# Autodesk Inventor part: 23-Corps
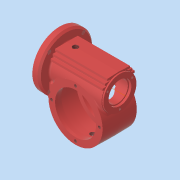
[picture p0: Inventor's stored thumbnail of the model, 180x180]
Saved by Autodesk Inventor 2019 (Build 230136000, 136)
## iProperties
Created: 2023-02
Part Number: 23-Corps
Material: Générique
Document SubType Name: Modeling
Designer: Thier
Density: 1 g/cm^3
Appearance: Lisse - Rouge
Author: Thier
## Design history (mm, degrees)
revolve "Révolution1" stored, may be unused: angle "d8" = 90 deg
sketch "Esquisse2"
  geometry: L1 (108.863, -25)-(108.863, 25) reference; C1 r 48 at (60.863, -40.6); 1 further point
  constraints: 1 centre point
  dimensions: "d9" = 40.6 vertical distance of C1.centre point (0, 0); "d10" = 96 diameter of C1; "d11" = 48 distance from line of C1.centre L1
extrude "Extrusion1" join sketch "Esquisse2" stored distance "d12" = 60; taper "d13" = -1 deg
sketch "Esquisse3"
  geometry: C1 r 46 at (60.863, -40.6); 5 further points
  constraints: 1 centre point, 2 other
  dimensions: "d14" = 92 diameter of C1
extrude "Extrusion2" cut sketch "Esquisse3" stored distance "d15" = 34; taper "d16" = -1 deg
sketch "Esquisse4"
  geometry: C1 r 38 at (60.863, -40.6); A1 r 48 centre (60.863, -40.6) between (13.437, -48) and (107.44, -29) reference; 2 further points
  constraints: 1 centre point, 1 concentric
  dimensions: "d17" = 76 diameter of C1
extrude "Extrusion3" cut sketch "Esquisse4" stored distance "d18" = 50; taper "d19" = 0 deg
sketch "Esquisse5"
  geometry: C1 r 36 at (60.863, -40.6); 5 further points
  constraints: 1 centre point, 2 other
  dimensions: "d20" = 72 diameter of C1
extrude "Extrusion4" cut sketch "Esquisse5" extent not by distance; stored distance "d21" = 50; taper "d22" = 0 deg
sketch "Esquisse9"
  geometry: C1 r 29 at (0, 0); C2 r 18 at (0, 0); 1 further point
  constraints: 2 centre point, 2 coincident
  dimensions: "d37" = 58 diameter of C1; "d38" = 36 diameter of C2
extrude "Extrusion7" join sketch "Esquisse9" distance "d39" = 19; taper "d40" = 0 deg
sketch "Esquisse12"
  geometry: C1 r 36 at (-60.863, -40.6); C2 r 36 at (-60.863, -40.6) reference; 1 further point
  constraints: 1 centre point, 1 concentric
  dimensions: "d47" = 72 diameter of C1
extrude "Extrusion10" cut sketch "Esquisse12" extent not by distance; stored distance "d48" = 8; taper "d49" = 0 deg
sketch "Esquisse13"
  geometry: C1 r 38 at (0, 0); C2 r 36 at (0, 0) reference; 1 further point
  constraints: 1 centre point, 1 concentric
  dimensions: "d50" = 76 diameter of C1
extrude "Extrusion11" cut sketch "Esquisse13" distance "d51" = 50; taper "d52" = 0 deg
chamfer "Chanfrein1" distance "d53" = 8; stored, may be unused: second distance "d54" = 1, angle "d55" = 45 deg
chamfer "Chanfrein2" distance "d56" = 8; stored, may be unused: second distance "d57" = 1, angle "d58" = 45 deg
chamfer "Chanfrein3" distance "d59" = 3; stored, may be unused: second distance "d60" = 1, angle "d61" = 45 deg
sketch "Esquisse14" dims "d63" = 84
  geometry: L1 (60.863, -40.6)-(60.863, 1.4); L2 (60.863, -38.664)-(60.863, 43.315); C1 r 36 at (60.863, -40.6) reference; 3 further points
  constraints: 4 end point, 2 coincident, 1 point on line, 1 vertical, 1 vertical alignment, 2 other
  dimensions: "d74" = 0 distance between parallel lines of L2 L1
hole "Perçage1" sketch "Esquisse14" at (60.863, 1.4) diameter "d64" = 4.917; stored, may be unused: countersink angle "d68" = 90 deg, drill point angle "d70" = 118 deg; dims "d65" = 12, "d66" = 4, "d67" = 2, "d69" = 8
pattern_circular "Réseau circulaire1" dims angle "d72" = 360 deg
sketch "Esquisse17"
  geometry: C1 r 18 at (0, 0); 1 further point
  constraints: 1 centre point, 1 coincident
extrude "Extrusion13" cut sketch "Esquisse17" extent not by distance; stored distance "d87" = 50; taper "d88" = 0 deg
sketch "Esquisse18"
  geometry: C1 r 20 at (0, 0); 1 further point
  constraints: 1 centre point, 1 coincident
extrude "Extrusion14" cut sketch "Esquisse18" distance "d89" = 50; taper "d90" = 0 deg
sketch "Esquisse19"
  geometry: C1 r 20 at (0, 0) reference; 2 further points
  dimensions: "d98" = 0 horizontal distance of point (0, -25) C1.centre; "d99" = 25 distance of C1.centre point (0, -25)
hole "Perçage3" sketch "Esquisse19" at (0, -25) diameter "d91" = 4.134; stored, may be unused: countersink angle "d95" = 90 deg, drill point angle "d97" = 118 deg; dims "d92" = 10, "d93" = 4, "d94" = 2, "d96" = 14.2
pattern_circular "Réseau circulaire2" dims angle "d101" = 360 deg
sketch "Esquisse20" dims "d104" = 84.5
  geometry: L1 (0, 0)-(0, 16.222); L2 (0, 0)-(29.875, 29.875); 2 further points
  constraints: 4 end point, 2 coincident, 1 vertical, 3 other
  dimensions: "d103" = 45 deg angle of L2 L1
hole "Perçage4" sketch "Esquisse20" diameter "d105" = 6.647; stored, may be unused: countersink angle "d109" = 90 deg, drill point angle "d111" = 118 deg; dims "d106" = 10, "d107" = 4, "d108" = 2, "d110" = 12
pattern_circular "Réseau circulaire3" dims angle "d113" = 360 deg
sketch "Esquisse22"
  geometry: L1 (-60.863, -17)-(-18.863, -17); L2 (-18.863, -17)-(-18.863, 17); L3 (-18.863, 17)-(-60.863, 17); L4 (-60.863, 17)-(-60.863, -17); L5 (-18.863, 20)-(-18.863, -20) reference; 3 further points
  constraints: 8 end point, 2 parallel, 1 horizontal, 1 perpendicular
  dimensions: "d117" = 17 distance from line of L1 point (0, 0); "d118" = 34 distance of L1.end L2.end; "d119" = 0 distance from line of L2.end L5
extrude "Extrusion15" cut sketch "Esquisse22" distance "d120" = 20; taper "d121" = 0 deg; dims "d138" = 10, "d139" = 0
chamfer "Chanfrein4" distance "d123" = 2; stored, may be unused: second distance "d124" = 1, angle "d125" = 45 deg
fillet "Congé2" dims "d126" = 3
fillet "Congé3" dims "d127" = 3
fillet "Congé4" dims "d128" = 3
fillet "Congé5" dims "d129" = 3
fillet "Congé6" dims "d130" = 3
fillet "Congé7" dims "d131" = 1, "d132" = 3
sketch "Esquisse23"
  geometry: C1 r 20 at (0, 0); 1 further point
  constraints: 1 centre point, 1 coincident
extrude "Extrusion16" cut sketch "Esquisse23" distance "d134" = 15; taper "d135" = 0 deg
fillet "Congé9" dims "d136" = 3
fillet "Congé10" dims "d137" = 3
fillet "Congé11" dims "d140" = 3
sketch "Esquisse24"
  geometry: L1 (0, 31)-(20, 29.952); L2 (20, 29.952)-(20, 26.452); L3 (20, 26.452)-(0, 26.452); L4 (0, 31)-(0, 26.452); L5 (24.067, 20.952)-(20.232, 20.952); L6 (12.401, 25.063)-(24.067, 24.452); L7 (24.067, 24.452)-(24.067, 20.952); L8 (28, 15.452)-(20.851, 15.452); L9 (20.796, 19.329)-(28, 18.952); L10 (28, 18.952)-(28, 15.452); L11 (0, 20.419)-(0, 15.452); L12 (14.278, 26.384)-(14.277, 26.452); L13 (20.851, 15.452)-(20.796, 19.329); C1 r 18 at (0, 0) reference; A1 r 30 centre (0, 0) between (19.715, -22.612) and (-24.508, -17.301) reference; A2 r 28.868 centre (0.372, 0) between (11.934, 26.452) and (0, 28.866); A3 r 28.868 centre (0.372, 0) between (24.757, 15.452) and (21.864, 19.273); A4 r 28.868 centre (0.372, 0) between (20.232, 20.952) and (14.927, 24.931); 2 further points
  constraints: 26 end point, 7 point on circle, 7 point on line, 3 centre point, 3 horizontal, 3 vertical, 2 perpendicular
  dimensions: "d141" = 93 deg angle of L2 L1; "d143" = 3.5 distance of L1.end L2.end; "d144" = 0 distance from line of C1.centre L4; "d145" = 31 distance of A1.centre L1.start; "d146" = 93 deg angle of L7 L6; "d148" = 3.5 distance of L6.end L5.start; "d149" = 93 deg angle of L10 L9; "d150" = 28 distance between parallel lines of L11 L10; "d151" = 3.5 distance of L9.end L8.start; "d152" = 2 distance from line of L6.end L3; "d155" = 2 vertical distance of L9.end L5.start
extrude "Extrusion17" join sketch "Esquisse24" stored distance "d156" = 10; taper "d157" = 0 deg
mirror "Symétrie3"
sketch "Esquisse25"
  geometry: L1 (30.863, 31)-(30.863, 23); L2 (30.863, 23)-(26.754, 23); L3 (26.754, 23)-(26.103, 31); L4 (26.103, 31)-(30.863, 31); L5 (2.863, -48)-(2.863, 48) reference; L6 (106.558, 31)-(15.627, 31) reference; 1 further point
  constraints: 8 end point, 2 perpendicular, 1 collinear, 1 vertical
  dimensions: "d159" = 8 distance of L1.start L1.end; "d161" = 4.65 deg angle of L1 L3; "d162" = 28 distance between parallel lines of L1 L5; "d191" = 4.76 distance of L3.end L1.start
revolve "Révolution2" sketch "Esquisse25" stored, may be unused: angle "d163" = 90 deg
feature "Filetage1" dims "d164" = 10, "d165" = 0
node "Point de construction1"
  node "Plan de construction1"
  node "Plan de construction2"
sketch "Esquisse26"
  geometry: L1 (-106.863, 0)-(-14.863, 0) reference; C1 r 7 at (-60.863, 0); 3 further points
  constraints: 1 centre point, 1 midpoint
  dimensions: "d168" = 14 diameter of C1
extrude "Extrusion18" join sketch "Esquisse26" stored distance "d169" = 10; taper "d170" = 0 deg
fillet "Congé13" dims "d171" = 3
hole "Perçage5" diameter "d174" = 8.566; stored, may be unused: countersink angle "d178" = 90 deg, drill point angle "d180" = 118 deg; dims "d175" = 19.456, "d176" = 4, "d177" = 2, "d179" = 23.956, "d192" = 10, "d193" = 10
fillet "Congé14" dims "d181" = 3
fillet "Congé15" dims "d182" = 3
sketch "Esquisse27"
  geometry: L1 (60.863, -40.579)-(103.153, -82.869); L2 (60.863, 1.4)-(60.863, -82.558); L3 (79.179, -64.552)-(95.609, -80.982); L4 (79.179, -64.552)-(82.008, -61.724); L5 (95.609, -80.982)-(98.438, -78.154); C1 r 2.458 at (60.863, 1.4) reference; C2 r 2.458 at (60.863, -82.6) reference; C3 r 9.975 at (60.863, -40.6); C4 r 36 at (60.863, -40.6) reference; 1 further point
  constraints: 10 end point, 2 midpoint, 1 centre point, 1 concentric, 1 parallel, 1 perpendicular, 1 point on line, 1 vertical
  dimensions: "d183" = 45 deg angle of L1 L2; "d184" = 8 diameter of L3 L1
revolve "Révolution3" sketch "Esquisse27" stored, may be unused: angle "d185" = 90 deg
feature "Filetage2" dims "d186" = 10, "d187" = 0
fillet "Congé16" dims "d188" = 1, "d189" = 3
fillet "Congé17" dims "d190" = 3
node "Solide1"
sketch "Esquisse1"
  geometry: L1 (2.863, 48)-(14.863, 48); L2 (14.863, 48)-(14.863, 30); L3 (14.863, 30)-(106.558, 30); L4 (106.558, 30)-(106.558, 29); L5 (108.863, 20)-(91.863, 20); L6 (91.863, 20)-(91.863, 18); L7 (91.863, 18)-(85.863, 18); L8 (85.863, 18)-(85.863, 25); L9 (85.863, 25)-(18.863, 25); L10 (18.863, 25)-(18.863, 20); L11 (18.863, 20)-(7.863, 20); L12 (7.863, 20)-(7.863, 32.5); L13 (7.863, 32.5)-(5.863, 32.5); L14 (5.863, 32.5)-(5.863, 36.5); L15 (5.863, 36.5)-(2.863, 36.5); L16 (2.863, 36.5)-(2.863, 48); L17 (0, 0)-(119.271, 0); L18 (108.863, 29)-(106.558, 29); L19 (108.863, 20)-(108.863, 29)
  constraints: 38 end point, 11 perpendicular, 3 horizontal, 3 parallel, 1 vertical
  dimensions: "d0" = 17 distance of L5.start L5.end; "d2" = 6 distance of L6.end L7.end; "d3" = 11 distance of L10.end L11.end; "d4" = 2 distance of L12.end L13.end; "d5" = 3 distance of L14.end L15.end; "d6" = 12 distance of L1.start L1.end; "d23" = 40 diameter of L5 L17; "d24" = 36 diameter of L7 L17; "d25" = 40 diameter of L11 L17; "d26" = 65 diameter of L13 L17; "d27" = 73 diameter of L15 L17; "d28" = 96 diameter of L1 L17; "d29" = 60 diameter of L3 L17; "d30" = 50 diameter of L9 L17; "d84" = 58 diameter of L18 L17
other parameters: "d166" = -92, "d167" = -58
